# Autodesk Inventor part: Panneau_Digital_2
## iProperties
Created: 2009-02
Part Number: Panneau_Digital_2
Material: UHMW - Noir
Document SubType Name: Modeling
Designer: Alex_Cyril
Author: Alex_Cyril
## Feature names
1. Extrusion1
